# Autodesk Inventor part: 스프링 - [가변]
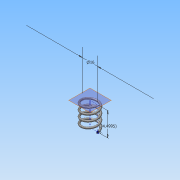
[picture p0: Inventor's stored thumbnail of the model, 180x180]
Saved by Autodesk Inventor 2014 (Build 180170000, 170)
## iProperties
Created: 2015-04
Part Number: 스프링 - [가변]
Material: 강철, 탄소
Document SubType Name: Modeling
Designer: Administrator
Density: 7.87 g/cm^3
Appearance: 반연마
Mass: 4.885 g
Surface Area: 12.6425 cm^2
Volume: 0.620712 cm^3
Author: Administrator
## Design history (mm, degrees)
sketch "스케치1"
  geometry: L1 (0, 0)-(8, 0); L2 (8, 0)-(8, 24.5); L3 (8, 24.5)-(0, 24.5); L4 (0, 24.5)-(0, 0); C1 r 1 at (8, 0)
  constraints: 8 end point, 2 parallel, 1 centre point, 1 coincident, 1 horizontal, 1 perpendicular
  dimensions: "d0" = 16 diameter of L2 L4; "d1" = 24.49951 distance between parallel lines of L1 L3 (derived); "d2" = 2 diameter of C1
feature "코일1" pitch "d3" = 10; turns "d5" = 4; dims "d4" = 24.49951 (= d1), "d6" = 0, angle "d7" = 90 deg, angle "d8" = 90 deg, "d9" = 0, "d10" = 0
sketch "스케치2"
  geometry: L1 (-9, 0)-(-7, 0) reference; 1 further point
  constraints: 1 horizontal alignment
extrude "돌출1" cut sketch "스케치2" stored distance "d11" = 10; taper "d12" = 0 deg
node "작업 평면1"
sketch "스케치3"
  geometry: L1 (9, 0)-(7, 0) reference; 1 further point
  constraints: 1 horizontal alignment
extrude "돌출2" cut sketch "스케치3" stored distance "d13" = 10; taper "d14" = 0 deg
node "솔리드1"
node "절단 모서리 투영1"
node "절단 모서리 투영2"
